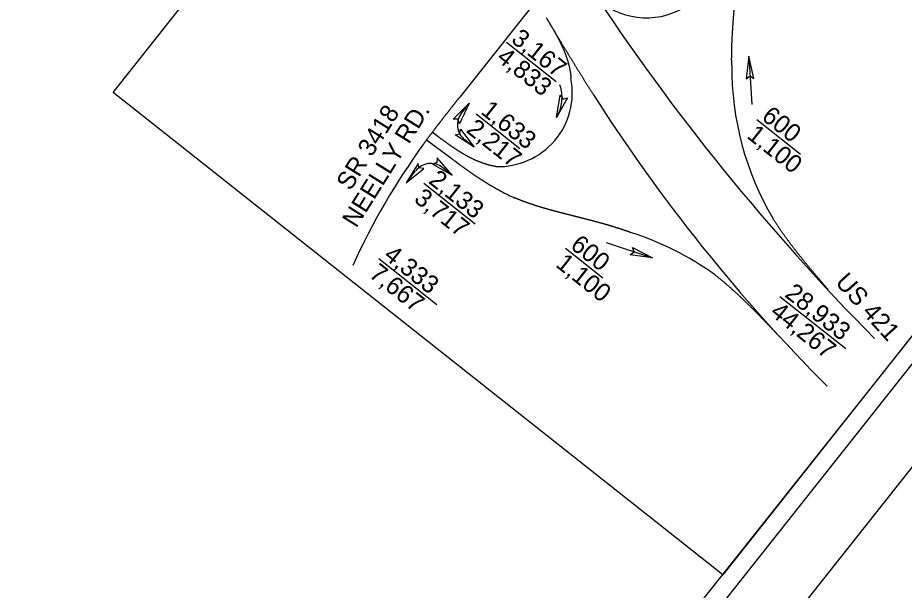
# Model space of a CAD drawing. Extents: x 1771636 to 1784627, y 798645 to 819978.
# Drawn here: x 1783444.1 to 1783789.1, y 811819.1 to 812041.9 of the extents above; entities that cross this region are included whole.
import ezdxf

# ---------------------------------------------------------------- set-up
doc = ezdxf.new("R2010")
doc.units = 0
for name, color, linetype in [('Exist Hydro Stream Flow Arrow CELL', 7, 'Continuous'), ('Exist Other Culture Well CELL', 7, 'Continuous'), ('Exist Structure Minor Footbridge', 7, 'Continuous'), ('Exist Utilities Power Joint Use Telephone CELL', 7, 'Continuous'), ('Exist Utilities Telephone Pole CELL', 7, 'Continuous')]:
    doc.layers.add(name, color=color, linetype=linetype)

msp = doc.modelspace()

# ---------------------------------------------------------------- linework, layer by layer
at = {"layer": 'Exist Hydro Stream Flow Arrow CELL'}
msp.add_lwpolyline([(1784297.88, 812505.92), (1781710.58, 814554.31), (1780665.28, 813234), (1783252.58, 811185.61)], close=True, dxfattribs=at)
at = {"layer": 'Exist Other Culture Well CELL'}
msp.add_lwpolyline([(1784457.99, 812708.16), (1781817.38, 814798.76), (1780451.82, 813073.93), (1783092.43, 810983.33)], close=True, dxfattribs=at)
at = {"layer": 'Exist Structure Minor Footbridge'}
for p, q in [((1783733.54, 812159.45), (1783616.05, 812011.05)), ((1783634.22, 812032.48), (1783653.56, 812017.17)), ((1783728.62, 812026.92), (1783729.74, 812008.21)), ((1783619.74, 812008.66), (1783616.77, 812004.95)), ((1783622.43, 812004.57), (1783639.46, 811991.09)), ((1783731.66, 812002.33), (1783748.69, 811988.85)), ((1783607.51, 811995.77), (1783605.38, 811997.35)), ((1783612.58, 811987.3), (1783603.1, 811994.3)), ((1783621.66, 811991.52), (1783618.04, 811994.37)), ((1783595.97, 811978.63), (1783598.89, 811982.38)), ((1783613.09, 811980.7), (1783609.49, 811983.57)), ((1783602.08, 811977.55), (1783622.05, 811961.74)), ((1783673.06, 811954.41), (1783691.09, 811948.45)), ((1783657.24, 811952.23), (1783671.81, 811940.69)), ((1783584.59, 811948.25), (1783607.21, 811930.35)), ((1783740.69, 811933.37), (1783766.27, 811913.12))]:
    msp.add_line(p, q, dxfattribs=at)
for points in [[(1783481.26, 812012.88), (1783654.22, 812231.34), (1783891.37, 812043.59), (1783718.41, 811825.12)], [(1783730.56, 812018.32), (1783728.62, 812026.92), (1783727.56, 812018.14), (1783729.07, 812019.34)], [(1783657.99, 812010.82), (1783653.7, 812003.12), (1783655.16, 812011.84), (1783656.28, 812010.26)], [(1783613.48, 812002.46), (1783619.75, 812008.65), (1783615.91, 812000.69), (1783615.28, 812002.52)], [(1783616.32, 811998.54), (1783621.66, 811991.52), (1783614.25, 811996.36), (1783616.15, 811996.75)], [(1783599.84, 811985.21), (1783595.25, 811977.69), (1783602.12, 811983.26), (1783600.2, 811983.45)], [(1783605.4, 811985.01), (1783613.09, 811980.7), (1783607.27, 811987.36), (1783607.15, 811985.44)], [(1783683.28, 811952.53), (1783691.09, 811948.45), (1783682.33, 811949.67), (1783683.88, 811950.83)]]:
    msp.add_lwpolyline(points, close=True, dxfattribs=at)
for centre, radius, start, end in [((1783688.74, 812070.72), 28.82, 229.6953, 21.0453), ((1784414.38, 812546.24), 895.25, 213.34167, 224.65417), ((1783837.78, 812022.62), 115.87, 179.5447, 210.4698), ((1783631.12, 812012.77), 28.77, 268.0973, 11.1037), ((1783641.61, 812010.78), 14.31, 327.6317, 20.7866), ((1784234.37, 812372.73), 671.43, 212.5, 224.92859), ((1783622.67, 812000.26), 7.5, 141.6309, 231.8342), ((1783822.92, 811832.32), 273.05, 144.09, 155.5073), ((1783604.82, 811977.71), 7.5, 51.4277, 141.6309), ((1783667.43, 812041.85), 76.17, 242.364, 247.0041), ((1783647.41, 811847.54), 116.25, 54.2989, 72.4038)]:
    msp.add_arc(centre, radius, start, end, dxfattribs=at)
for points in [[(1783721.91, 812023.54), (1783721.9, 812023.86), (1783721.9, 812024.18), (1783721.89, 812024.49), (1783721.89, 812024.81), (1783721.89, 812025.13), (1783721.89, 812025.44), (1783721.88, 812025.76), (1783721.88, 812026.08), (1783721.89, 812026.39), (1783721.89, 812026.71), (1783721.89, 812027.03), (1783721.89, 812027.34), (1783721.89, 812027.66), (1783721.9, 812027.98), (1783721.9, 812028.29), (1783721.91, 812028.61), (1783721.92, 812028.93), (1783721.92, 812029.24), (1783721.93, 812029.56), (1783721.94, 812029.88), (1783721.95, 812030.19), (1783721.96, 812030.51), (1783721.97, 812030.83), (1783721.98, 812031.14), (1783721.99, 812031.46), (1783722, 812031.78), (1783722.01, 812032.09), (1783722.03, 812032.41), (1783722.04, 812032.73), (1783722.05, 812033.04), (1783722.07, 812033.36), (1783722.08, 812033.68), (1783722.1, 812033.99), (1783722.11, 812034.31), (1783722.13, 812034.62), (1783722.15, 812034.94), (1783722.16, 812035.26), (1783722.18, 812035.57), (1783722.2, 812035.89), (1783722.22, 812036.21), (1783722.24, 812036.52), (1783722.26, 812036.84), (1783722.28, 812037.15), (1783722.3, 812037.47), (1783722.32, 812037.79), (1783722.34, 812038.1), (1783722.36, 812038.42), (1783722.38, 812038.73), (1783722.4, 812039.05), (1783722.42, 812039.37), (1783722.45, 812039.68), (1783722.47, 812040), (1783722.49, 812040.31), (1783722.51, 812040.63), (1783722.54, 812040.95), (1783722.56, 812041.26), (1783722.58, 812041.58), (1783722.61, 812041.89), (1783722.63, 812042.21), (1783722.66, 812042.53), (1783722.68, 812042.84), (1783722.71, 812043.16), (1783722.73, 812043.47), (1783722.76, 812043.79), (1783722.78, 812044.1), (1783722.81, 812044.42), (1783722.83, 812044.74), (1783722.86, 812045.05), (1783722.88, 812045.37), (1783722.91, 812045.68), (1783722.93, 812046), (1783722.96, 812046.31), (1783722.98, 812046.63), (1783723.01, 812046.95)], [(1783649.72, 812041.95), (1783649.9, 812041.65), (1783650.08, 812041.35), (1783650.26, 812041.05), (1783650.44, 812040.76), (1783650.62, 812040.46), (1783650.8, 812040.16), (1783650.98, 812039.86), (1783651.16, 812039.56), (1783651.34, 812039.26), (1783651.52, 812038.96), (1783651.7, 812038.66), (1783651.88, 812038.37), (1783652.05, 812038.06), (1783652.23, 812037.76), (1783652.4, 812037.46), (1783652.58, 812037.16), (1783652.75, 812036.86), (1783652.93, 812036.56), (1783653.1, 812036.25), (1783653.27, 812035.95), (1783653.44, 812035.65), (1783653.61, 812035.34), (1783653.77, 812035.04), (1783653.94, 812034.73), (1783654.11, 812034.42), (1783654.27, 812034.12), (1783654.43, 812033.81), (1783654.59, 812033.5), (1783654.75, 812033.19), (1783654.91, 812032.88), (1783655.07, 812032.57), (1783655.22, 812032.25), (1783655.37, 812031.94), (1783655.52, 812031.63), (1783655.67, 812031.31), (1783655.82, 812031), (1783655.97, 812030.68), (1783656.11, 812030.36), (1783656.25, 812030.04), (1783656.39, 812029.72), (1783656.52, 812029.4), (1783656.66, 812029.08), (1783656.79, 812028.76), (1783656.92, 812028.44), (1783657.05, 812028.11), (1783657.17, 812027.79), (1783657.29, 812027.46), (1783657.41, 812027.13), (1783657.53, 812026.8), (1783657.64, 812026.47), (1783657.75, 812026.14), (1783657.86, 812025.81), (1783657.96, 812025.48), (1783658.07, 812025.15), (1783658.16, 812024.81), (1783658.26, 812024.48), (1783658.35, 812024.14), (1783658.44, 812023.8), (1783658.53, 812023.47), (1783658.61, 812023.13), (1783658.69, 812022.79), (1783658.76, 812022.45), (1783658.83, 812022.11), (1783658.9, 812021.77), (1783658.96, 812021.42), (1783659.02, 812021.08), (1783659.08, 812020.74), (1783659.13, 812020.39), (1783659.17, 812020.05), (1783659.22, 812019.7), (1783659.26, 812019.35), (1783659.29, 812019.01), (1783659.32, 812018.66), (1783659.35, 812018.31)], [(1783649.72, 812041.95), (1783649.96, 812041.54), (1783650.21, 812041.13), (1783650.45, 812040.73), (1783650.7, 812040.32), (1783650.94, 812039.91), (1783651.19, 812039.5), (1783651.43, 812039.1), (1783651.68, 812038.69), (1783651.92, 812038.28), (1783652.17, 812037.88), (1783652.41, 812037.47), (1783652.66, 812037.06), (1783652.9, 812036.65), (1783653.15, 812036.25), (1783653.39, 812035.84), (1783653.64, 812035.43), (1783653.88, 812035.03), (1783654.13, 812034.62), (1783654.37, 812034.21), (1783654.62, 812033.81), (1783654.86, 812033.4), (1783655.11, 812032.99), (1783655.36, 812032.59), (1783655.6, 812032.18), (1783655.85, 812031.77), (1783656.09, 812031.37), (1783656.34, 812030.96), (1783656.59, 812030.55), (1783656.83, 812030.15), (1783657.08, 812029.74), (1783657.32, 812029.33), (1783657.57, 812028.93), (1783657.82, 812028.52), (1783658.07, 812028.12), (1783658.31, 812027.71), (1783658.56, 812027.31), (1783658.81, 812026.9), (1783659.05, 812026.49), (1783659.3, 812026.09), (1783659.55, 812025.68), (1783659.8, 812025.28), (1783660.05, 812024.87), (1783660.29, 812024.47), (1783660.54, 812024.06), (1783660.79, 812023.66), (1783661.04, 812023.25), (1783661.29, 812022.85), (1783661.54, 812022.44), (1783661.79, 812022.04), (1783662.04, 812021.63), (1783662.29, 812021.23), (1783662.53, 812020.83), (1783662.79, 812020.42), (1783663.04, 812020.02), (1783663.29, 812019.62), (1783663.54, 812019.21), (1783663.79, 812018.81), (1783664.04, 812018.4), (1783664.29, 812018), (1783664.54, 812017.6), (1783664.79, 812017.2), (1783665.04, 812016.79), (1783665.3, 812016.39), (1783665.55, 812015.99), (1783665.8, 812015.59), (1783666.06, 812015.18), (1783666.31, 812014.78), (1783666.56, 812014.38), (1783666.82, 812013.98), (1783667.07, 812013.58), (1783667.32, 812013.18), (1783667.58, 812012.77), (1783667.83, 812012.37), (1783668.09, 812011.97)], [(1783616.05, 812011.05), (1783615.85, 812010.8), (1783615.65, 812010.55), (1783615.46, 812010.31), (1783615.26, 812010.06), (1783615.06, 812009.81), (1783614.87, 812009.56), (1783614.67, 812009.31), (1783614.47, 812009.06), (1783614.28, 812008.82), (1783614.08, 812008.57), (1783613.89, 812008.32), (1783613.69, 812008.07), (1783613.49, 812007.82), (1783613.3, 812007.57), (1783613.1, 812007.32), (1783612.9, 812007.08), (1783612.71, 812006.83), (1783612.51, 812006.58), (1783612.32, 812006.33), (1783612.12, 812006.08), (1783611.92, 812005.83), (1783611.73, 812005.58), (1783611.53, 812005.33), (1783611.34, 812005.08), (1783611.14, 812004.83), (1783610.95, 812004.58), (1783610.75, 812004.34), (1783610.56, 812004.09), (1783610.36, 812003.84), (1783610.17, 812003.59), (1783609.97, 812003.34), (1783609.78, 812003.09), (1783609.58, 812002.84), (1783609.39, 812002.59), (1783609.19, 812002.34), (1783609, 812002.09), (1783608.81, 812001.84), (1783608.61, 812001.59), (1783608.42, 812001.34), (1783608.23, 812001.08), (1783608.03, 812000.83), (1783607.84, 812000.58), (1783607.65, 812000.33), (1783607.45, 812000.08), (1783607.26, 811999.83), (1783607.07, 811999.58), (1783606.87, 811999.33), (1783606.68, 811999.07), (1783606.49, 811998.82), (1783606.3, 811998.57), (1783606.11, 811998.32), (1783605.92, 811998.07), (1783605.72, 811997.81), (1783605.53, 811997.56), (1783605.34, 811997.31), (1783605.15, 811997.05), (1783604.96, 811996.8), (1783604.77, 811996.55), (1783604.58, 811996.3), (1783604.39, 811996.04), (1783604.2, 811995.79), (1783604.01, 811995.53), (1783603.83, 811995.28), (1783603.64, 811995.02), (1783603.45, 811994.77), (1783603.26, 811994.52), (1783603.07, 811994.26), (1783602.88, 811994.01), (1783602.7, 811993.75), (1783602.51, 811993.49), (1783602.32, 811993.24), (1783602.14, 811992.98), (1783601.95, 811992.73), (1783601.76, 811992.47)], [(1783630.16, 811984.02), (1783629.82, 811984.08), (1783629.48, 811984.14), (1783629.14, 811984.21), (1783628.79, 811984.28), (1783628.45, 811984.35), (1783628.11, 811984.43), (1783627.78, 811984.51), (1783627.44, 811984.6), (1783627.1, 811984.69), (1783626.77, 811984.79), (1783626.43, 811984.88), (1783626.1, 811984.99), (1783625.77, 811985.09), (1783625.44, 811985.2), (1783625.11, 811985.31), (1783624.78, 811985.43), (1783624.45, 811985.55), (1783624.12, 811985.67), (1783623.8, 811985.79), (1783623.48, 811985.92), (1783623.15, 811986.05), (1783622.83, 811986.19), (1783622.51, 811986.33), (1783622.19, 811986.47), (1783621.88, 811986.61), (1783621.56, 811986.76), (1783621.24, 811986.9), (1783620.93, 811987.06), (1783620.62, 811987.21), (1783620.31, 811987.37), (1783620, 811987.52), (1783619.69, 811987.69), (1783619.38, 811987.85), (1783619.07, 811988.01), (1783618.77, 811988.18), (1783618.46, 811988.35), (1783618.16, 811988.52), (1783617.86, 811988.7), (1783617.56, 811988.87), (1783617.26, 811989.05), (1783616.96, 811989.23), (1783616.66, 811989.41), (1783616.36, 811989.59), (1783616.07, 811989.77), (1783615.77, 811989.96), (1783615.48, 811990.15), (1783615.18, 811990.34), (1783614.89, 811990.53), (1783614.6, 811990.72), (1783614.31, 811990.91), (1783614.02, 811991.1), (1783613.73, 811991.3), (1783613.44, 811991.49), (1783613.16, 811991.69), (1783612.87, 811991.89), (1783612.58, 811992.09), (1783612.3, 811992.29), (1783612.01, 811992.49), (1783611.73, 811992.69), (1783611.45, 811992.89), (1783611.16, 811993.09), (1783610.88, 811993.3), (1783610.6, 811993.5), (1783610.32, 811993.71), (1783610.03, 811993.91), (1783609.75, 811994.12), (1783609.47, 811994.32), (1783609.19, 811994.53), (1783608.91, 811994.74), (1783608.63, 811994.94), (1783608.35, 811995.15), (1783608.07, 811995.36), (1783607.79, 811995.56), (1783607.51, 811995.77)], [(1783632.1, 811974.37), (1783631.82, 811974.52), (1783631.54, 811974.66), (1783631.26, 811974.81), (1783630.98, 811974.97), (1783630.7, 811975.12), (1783630.42, 811975.27), (1783630.15, 811975.42), (1783629.87, 811975.58), (1783629.6, 811975.74), (1783629.32, 811975.89), (1783629.05, 811976.05), (1783628.77, 811976.21), (1783628.5, 811976.37), (1783628.23, 811976.53), (1783627.95, 811976.69), (1783627.68, 811976.86), (1783627.41, 811977.02), (1783627.14, 811977.18), (1783626.87, 811977.35), (1783626.6, 811977.52), (1783626.33, 811977.68), (1783626.06, 811977.85), (1783625.8, 811978.02), (1783625.53, 811978.19), (1783625.26, 811978.36), (1783624.99, 811978.53), (1783624.73, 811978.7), (1783624.46, 811978.87), (1783624.2, 811979.05), (1783623.93, 811979.22), (1783623.67, 811979.4), (1783623.4, 811979.57), (1783623.14, 811979.75), (1783622.88, 811979.92), (1783622.61, 811980.1), (1783622.35, 811980.28), (1783622.09, 811980.45), (1783621.83, 811980.63), (1783621.57, 811980.81), (1783621.31, 811980.99), (1783621.05, 811981.17), (1783620.79, 811981.35), (1783620.53, 811981.53), (1783620.27, 811981.71), (1783620.01, 811981.9), (1783619.75, 811982.08), (1783619.49, 811982.26), (1783619.23, 811982.45), (1783618.97, 811982.63), (1783618.71, 811982.81), (1783618.46, 811983), (1783618.2, 811983.18), (1783617.94, 811983.37), (1783617.69, 811983.55), (1783617.43, 811983.74), (1783617.17, 811983.92), (1783616.92, 811984.11), (1783616.66, 811984.29), (1783616.4, 811984.48), (1783616.15, 811984.67), (1783615.89, 811984.85), (1783615.64, 811985.04), (1783615.38, 811985.23), (1783615.13, 811985.42), (1783614.87, 811985.6), (1783614.62, 811985.79), (1783614.36, 811985.98), (1783614.11, 811986.17), (1783613.85, 811986.35), (1783613.6, 811986.54), (1783613.34, 811986.73), (1783613.09, 811986.92), (1783612.83, 811987.11), (1783612.58, 811987.3)], [(1783660.05, 811964.84), (1783659.74, 811964.92), (1783659.43, 811965), (1783659.13, 811965.07), (1783658.82, 811965.15), (1783658.51, 811965.23), (1783658.21, 811965.31), (1783657.9, 811965.38), (1783657.59, 811965.46), (1783657.28, 811965.54), (1783656.98, 811965.62), (1783656.67, 811965.7), (1783656.36, 811965.78), (1783656.06, 811965.85), (1783655.75, 811965.93), (1783655.44, 811966.01), (1783655.14, 811966.09), (1783654.83, 811966.17), (1783654.52, 811966.25), (1783654.22, 811966.33), (1783653.91, 811966.41), (1783653.61, 811966.5), (1783653.3, 811966.58), (1783652.99, 811966.66), (1783652.69, 811966.74), (1783652.38, 811966.82), (1783652.08, 811966.91), (1783651.77, 811966.99), (1783651.47, 811967.08), (1783651.16, 811967.16), (1783650.86, 811967.25), (1783650.55, 811967.33), (1783650.25, 811967.42), (1783649.94, 811967.5), (1783649.64, 811967.59), (1783649.33, 811967.68), (1783649.03, 811967.77), (1783648.72, 811967.86), (1783648.42, 811967.95), (1783648.12, 811968.04), (1783647.81, 811968.13), (1783647.51, 811968.22), (1783647.21, 811968.31), (1783646.9, 811968.4), (1783646.6, 811968.5), (1783646.3, 811968.59), (1783646, 811968.69), (1783645.7, 811968.78), (1783645.39, 811968.88), (1783645.09, 811968.98), (1783644.79, 811969.08), (1783644.49, 811969.18), (1783644.19, 811969.28), (1783643.89, 811969.38), (1783643.59, 811969.48), (1783643.29, 811969.58), (1783642.99, 811969.69), (1783642.69, 811969.79), (1783642.39, 811969.9), (1783642.1, 811970), (1783641.8, 811970.11), (1783641.5, 811970.22), (1783641.2, 811970.33), (1783640.91, 811970.44), (1783640.61, 811970.55), (1783640.32, 811970.67), (1783640.02, 811970.78), (1783639.72, 811970.89), (1783639.43, 811971.01), (1783639.14, 811971.13), (1783638.84, 811971.25), (1783638.55, 811971.37), (1783638.26, 811971.49), (1783637.96, 811971.61), (1783637.67, 811971.73)], [(1783682.56, 811958.35), (1783682.26, 811958.45), (1783681.96, 811958.56), (1783681.66, 811958.67), (1783681.36, 811958.77), (1783681.06, 811958.88), (1783680.76, 811958.98), (1783680.47, 811959.08), (1783680.17, 811959.18), (1783679.87, 811959.29), (1783679.57, 811959.39), (1783679.26, 811959.49), (1783678.96, 811959.59), (1783678.66, 811959.68), (1783678.36, 811959.78), (1783678.06, 811959.88), (1783677.76, 811959.98), (1783677.46, 811960.07), (1783677.15, 811960.17), (1783676.85, 811960.26), (1783676.55, 811960.36), (1783676.25, 811960.45), (1783675.94, 811960.54), (1783675.64, 811960.64), (1783675.34, 811960.73), (1783675.04, 811960.82), (1783674.73, 811960.91), (1783674.43, 811961), (1783674.12, 811961.09), (1783673.82, 811961.18), (1783673.52, 811961.27), (1783673.21, 811961.36), (1783672.91, 811961.44), (1783672.6, 811961.53), (1783672.3, 811961.62), (1783671.99, 811961.7), (1783671.69, 811961.79), (1783671.38, 811961.87), (1783671.08, 811961.96), (1783670.77, 811962.04), (1783670.47, 811962.13), (1783670.16, 811962.21), (1783669.86, 811962.3), (1783669.55, 811962.38), (1783669.25, 811962.46), (1783668.94, 811962.54), (1783668.63, 811962.63), (1783668.33, 811962.71), (1783668.02, 811962.79), (1783667.72, 811962.87), (1783667.41, 811962.95), (1783667.1, 811963.03), (1783666.8, 811963.11), (1783666.49, 811963.19), (1783666.19, 811963.27), (1783665.88, 811963.35), (1783665.57, 811963.43), (1783665.27, 811963.51), (1783664.96, 811963.59), (1783664.65, 811963.67), (1783664.35, 811963.75), (1783664.04, 811963.83), (1783663.73, 811963.91), (1783663.42, 811963.98), (1783663.12, 811964.06), (1783662.81, 811964.14), (1783662.5, 811964.22), (1783662.2, 811964.3), (1783661.89, 811964.37), (1783661.58, 811964.45), (1783661.28, 811964.53), (1783660.97, 811964.61), (1783660.66, 811964.68), (1783660.35, 811964.76), (1783660.05, 811964.84)], [(1783759.43, 811936.11), (1783759.12, 811936.47), (1783758.81, 811936.83), (1783758.5, 811937.19), (1783758.19, 811937.55), (1783757.88, 811937.91), (1783757.57, 811938.27), (1783757.26, 811938.63), (1783756.95, 811938.99), (1783756.64, 811939.36), (1783756.33, 811939.72), (1783756.03, 811940.08), (1783755.72, 811940.44), (1783755.41, 811940.8), (1783755.1, 811941.16), (1783754.79, 811941.53), (1783754.49, 811941.89), (1783754.18, 811942.25), (1783753.87, 811942.61), (1783753.57, 811942.98), (1783753.26, 811943.34), (1783752.96, 811943.71), (1783752.65, 811944.07), (1783752.35, 811944.43), (1783752.04, 811944.8), (1783751.74, 811945.16), (1783751.44, 811945.53), (1783751.13, 811945.9), (1783750.83, 811946.26), (1783750.53, 811946.63), (1783750.23, 811947), (1783749.93, 811947.37), (1783749.63, 811947.74), (1783749.33, 811948.11), (1783749.03, 811948.47), (1783748.74, 811948.85), (1783748.44, 811949.22), (1783748.14, 811949.59), (1783747.85, 811949.96), (1783747.55, 811950.33), (1783747.26, 811950.71), (1783746.97, 811951.08), (1783746.67, 811951.45), (1783746.38, 811951.83), (1783746.09, 811952.21), (1783745.8, 811952.58), (1783745.51, 811952.96), (1783745.23, 811953.34), (1783744.94, 811953.72), (1783744.65, 811954.1), (1783744.37, 811954.48), (1783744.09, 811954.86), (1783743.8, 811955.24), (1783743.52, 811955.62), (1783743.24, 811956.01), (1783742.96, 811956.39), (1783742.68, 811956.78), (1783742.41, 811957.16), (1783742.13, 811957.55), (1783741.86, 811957.94), (1783741.58, 811958.33), (1783741.31, 811958.72), (1783741.04, 811959.11), (1783740.77, 811959.5), (1783740.51, 811959.89), (1783740.24, 811960.28), (1783739.97, 811960.68), (1783739.71, 811961.07), (1783739.45, 811961.47), (1783739.19, 811961.87), (1783738.93, 811962.26), (1783738.67, 811962.66), (1783738.41, 811963.06), (1783738.16, 811963.46), (1783737.91, 811963.87)], [(1783740.62, 811917.65), (1783740.3, 811918), (1783739.97, 811918.35), (1783739.64, 811918.69), (1783739.32, 811919.04), (1783738.99, 811919.38), (1783738.66, 811919.73), (1783738.34, 811920.07), (1783738.01, 811920.42), (1783737.68, 811920.76), (1783737.36, 811921.1), (1783737.03, 811921.45), (1783736.7, 811921.79), (1783736.37, 811922.14), (1783736.05, 811922.48), (1783735.72, 811922.82), (1783735.39, 811923.17), (1783735.06, 811923.51), (1783734.73, 811923.85), (1783734.4, 811924.19), (1783734.07, 811924.54), (1783733.74, 811924.88), (1783733.41, 811925.22), (1783733.08, 811925.56), (1783732.75, 811925.9), (1783732.42, 811926.24), (1783732.08, 811926.58), (1783731.75, 811926.92), (1783731.42, 811927.26), (1783731.08, 811927.59), (1783730.75, 811927.93), (1783730.41, 811928.27), (1783730.08, 811928.6), (1783729.74, 811928.94), (1783729.4, 811929.27), (1783729.07, 811929.61), (1783728.73, 811929.94), (1783728.39, 811930.28), (1783728.05, 811930.61), (1783727.71, 811930.94), (1783727.37, 811931.27), (1783727.03, 811931.6), (1783726.69, 811931.93), (1783726.34, 811932.26), (1783726, 811932.59), (1783725.65, 811932.91), (1783725.31, 811933.24), (1783724.96, 811933.57), (1783724.62, 811933.89), (1783724.27, 811934.21), (1783723.92, 811934.54), (1783723.57, 811934.86), (1783723.22, 811935.18), (1783722.87, 811935.5), (1783722.52, 811935.82), (1783722.16, 811936.13), (1783721.81, 811936.45), (1783721.45, 811936.77), (1783721.1, 811937.08), (1783720.74, 811937.39), (1783720.38, 811937.71), (1783720.02, 811938.02), (1783719.66, 811938.33), (1783719.3, 811938.63), (1783718.94, 811938.94), (1783718.57, 811939.25), (1783718.21, 811939.55), (1783717.84, 811939.86), (1783717.48, 811940.16), (1783717.11, 811940.46), (1783716.74, 811940.76), (1783716.37, 811941.06), (1783716, 811941.35), (1783715.63, 811941.65), (1783715.25, 811941.94)]]:
    msp.add_spline(points, degree=3, dxfattribs=at)
at = {"layer": 'Exist Utilities Power Joint Use Telephone CELL'}
msp.add_lwpolyline([(1781915.64, 814370.28), (1784267.72, 812508.11), (1783243.53, 811214.46), (1780891.44, 813076.63)], close=True, dxfattribs=at)
at = {"layer": 'Exist Utilities Telephone Pole CELL'}
msp.add_lwpolyline([(1783384.75, 813185.41), (1782922.68, 812601.78), (1782968.4, 812565.53), (1783541.01, 812112.27), (1783700.51, 812313.71), (1783949.29, 812116.75), (1783784.11, 811908.02), (1783320.21, 811324), (1783286.6, 811356.67), (1783146.91, 811467.26), (1783125.11, 811467.64), (1783094.07, 811428.44), (1782948.68, 811547.66), (1782956.1, 811557.03), (1782756.79, 811714.83), (1782728.22, 811696.01), (1782447.03, 811920.16), (1782412.5, 811881.47), (1782072.85, 812146.5), (1782110.35, 812188.55), (1781507.48, 812669.12)], dxfattribs=at)

# ---------------------------------------------------------------- texts
at = {"layer": 'Exist Structure Minor Footbridge'}
for s, rotation, p in [('3,167', 321.6312, (1783635.68, 812032.77)), ('4,833', 321.6312, (1783629.99, 812025.58)), ('1,633', 321.6312, (1783623.89, 812004.86)), ('SR 3418', 57.9292, (1783573.52, 811974.23)), ('NEELLY RD.', 57.9292, (1783575.8, 811959.8)), ('600', 321.6312, (1783733.12, 812002.63)), ('2,217', 321.6312, (1783618.2, 811997.67)), ('1,100', 321.6312, (1783727.42, 811995.43)), ('2,133', 321.6312, (1783603.54, 811977.84)), ('3,717', 321.6312, (1783597.85, 811970.65)), ('600', 321.6312, (1783658.7, 811952.52)), ('4,333', 321.6312, (1783586.05, 811948.54)), ('7,667', 321.6312, (1783580.36, 811941.35)), ('1,100', 321.6312, (1783653, 811945.33)), ('US 421 ', 311.9061, (1783761.86, 811938.74)), ('28,933', 321.6312, (1783742.15, 811933.67)), ('44,267', 321.6312, (1783736.45, 811926.47))]:
    msp.add_text(s, height=7, rotation=rotation, dxfattribs=at).set_placement(p)
at = {"layer": 'Exist Utilities Power Joint Use Telephone CELL'}
msp.add_text('TO PLOT FULL SIZE 62"X34"', height=75, rotation=51.6309, dxfattribs=at).set_placement((1783719.07, 811003.39))

doc.saveas('drawing.dxf')
